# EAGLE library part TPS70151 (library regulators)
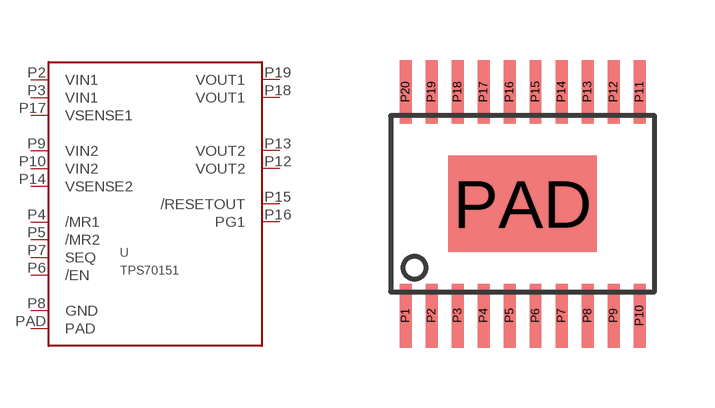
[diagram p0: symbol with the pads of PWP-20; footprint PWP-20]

Designator prefix U

## TPS70151  [PWP-20]
P2  VIN1  pwr
P3  VIN1  pwr
P4  /MR1  in
P5  /MR2  in
P6  /EN  in
P7  SEQ  in
P8  GND  pwr
P9  VIN2  pwr
P10  VIN2  pwr
P12  VOUT2  pwr
P13  VOUT2  pwr
P14  VSENSE2  pwr
P15  /RESETOUT  out
P16  PG1  out
P17  VSENSE1  pwr
P18  VOUT1  pwr
P19  VOUT1  pwr
PAD  PAD  pwr

## Footprint PWP-20 (pad centres in mm)
smd 0.3 x 1.6: P1 -2.925,-2.8; P2 -2.275,-2.8; P3 -1.625,-2.8; P4 -0.975,-2.8; P5 -0.325,-2.8; P6 0.325,-2.8; P7 0.975,-2.8; P8 1.625,-2.8; P9 2.275,-2.8; P10 2.925,-2.8; P11 2.925,2.8; P12 2.275,2.8; P13 1.625,2.8; P14 0.975,2.8; P15 0.325,2.8; P16 -0.325,2.8; P17 -0.975,2.8; P18 -1.625,2.8; P19 -2.275,2.8; P20 -2.925,2.8
smd 3.7 x 2.4: PAD 0,0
